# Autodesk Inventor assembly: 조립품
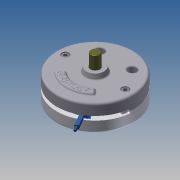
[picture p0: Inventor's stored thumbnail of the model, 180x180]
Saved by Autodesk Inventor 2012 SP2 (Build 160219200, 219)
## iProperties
Created: 2015-05
Part Number: 조립품
Document SubType Name: Assembly
Designer: Administrator
Author: Administrator
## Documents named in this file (10)
- C:\Users\Administrator\Desktop\Inventor2급\20150513-2급공용부품\조립품.iam
- C:\Users\Administrator\Desktop\Inventor2급\20150513-2급공용부품\본체.ipt
- C:\Users\Administrator\Desktop\Inventor2급\20150513-2급공용부품\베어링62_22.ipt
- C:\Users\Administrator\Desktop\Inventor2급\20150513-2급공용부품\축.ipt
- C:\Users\Administrator\Desktop\Inventor2급\20150513-2급공용부품\멈춤링.ipt
- C:\Users\Administrator\Desktop\Inventor2급\20150513-2급공용부품\슬라이더.ipt
- C:\Users\Administrator\Desktop\Inventor2급\20150513-2급공용부품\슬라이더2.ipt
- C:\Users\Administrator\Desktop\Inventor2급\20150513-2급공용부품\평행핀.ipt
- C:\Users\Administrator\Desktop\Inventor2급\20150513-2급공용부품\덮개.ipt
- C:\Users\Administrator\Desktop\Inventor2급\20150513-2급공용부품\M 10 x 35.ipt
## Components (2 placed, 1 different names)
1. M 10 x 35:1
2. M 10 x 35:2
